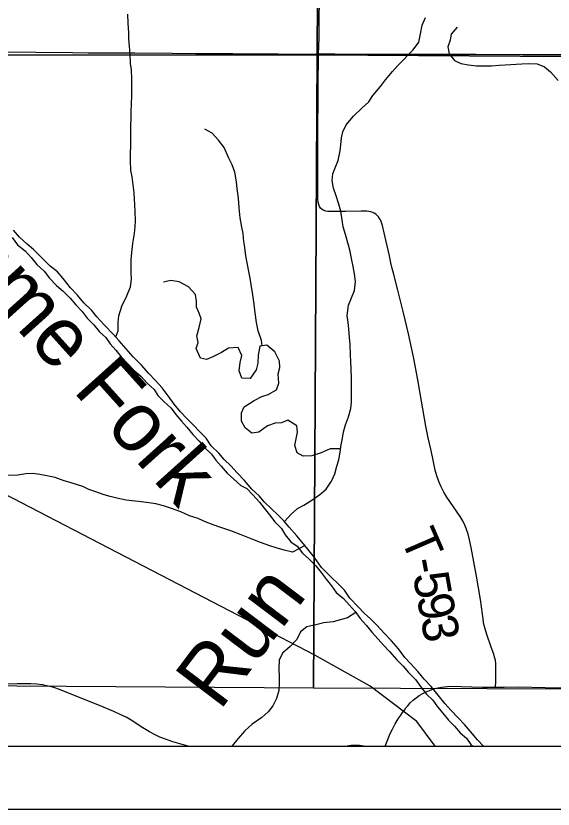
# Model space of a CAD drawing. Extents: x 0 to 34, y 0 to 22.
# Drawn here: x 10.139 to 10.993, y 9.078 to 10.337 of the extents above; entities that cross this region are included whole.
import ezdxf

# ---------------------------------------------------------------- set-up
doc = ezdxf.new("R2010")
doc.units = 0
for name, color, linetype in [('GM_X_County_Road', 7, 'Continuous'), ('GM_X_Interstate_Shield', 7, 'Continuous'), ('GM_X_Major_River', 7, 'Continuous'), ('GM_X_Major_River_Text', 7, 'Continuous'), ('GM_X_Minor_River', 7, 'Continuous'), ('GM_X_Minor_River_Text', 7, 'Continuous'), ('GM_X_Rail_Line', 7, 'Continuous'), ('GM_X_Section', 7, 'Continuous'), ('GM_X_Township_Road', 7, 'Continuous'), ('GM_X_Township_Road_Text', 7, 'Continuous'), ('GM_X_US_Route', 7, 'Continuous'), ('SH_Data', 7, 'Continuous')]:
    doc.layers.add(name, color=color, linetype=linetype)

msp = doc.modelspace()

# ---------------------------------------------------------------- linework, layer by layer
at = {"layer": 'GM_X_County_Road'}
msp.add_lwpolyline([(10.4132, 9.1775), (10.4036, 9.18), (10.3887, 9.1844), (10.3769, 9.1884), (10.3682, 9.1919), (10.3597, 9.1958), (10.3514, 9.2003), (10.3408, 9.2067), (10.3225, 9.2186), (10.3145, 9.2233), (10.3063, 9.2275), (10.295, 9.2326), (10.272, 9.2419), (10.2576, 9.2477), (10.2086, 9.2674), (10.1999, 9.2704), (10.1909, 9.2729), (10.1819, 9.2747), (10.1727, 9.2758), (10.1634, 9.2764), (10.151, 9.2765), (10.1417, 9.2764), (10.1231, 9.2761)], dxfattribs=at)
at = {"layer": 'GM_X_Interstate_Shield'}
msp.add_line((10.6653, 9.1775), (10.6917, 9.1775), dxfattribs=at)
msp.add_arc((10.6785, 9.1043), 0.0744, 79.7646, 100.2354, dxfattribs=at)
at = {"layer": 'GM_X_Major_River'}
for points in [[(10.8821, 9.1775), (10.8727, 9.1878), (10.8616, 9.2007), (10.8517, 9.212), (10.8415, 9.2226), (10.83, 9.2347), (10.8209, 9.2445), (10.8102, 9.2586), (10.7988, 9.2722), (10.7878, 9.2839), (10.7783, 9.2953), (10.7661, 9.3085), (10.7573, 9.3183), (10.7471, 9.332), (10.736, 9.3448), (10.725, 9.3566), (10.7128, 9.3698), (10.7025, 9.3796), (10.6926, 9.3887), (10.6828, 9.3985), (10.6698, 9.4125), (10.6611, 9.425), (10.6519, 9.4349), (10.6394, 9.4466), (10.6249, 9.4614), (10.6135, 9.4769), (10.6032, 9.4905), (10.5937, 9.5019), (10.5857, 9.5117), (10.5735, 9.5253), (10.5648, 9.5352), (10.5552, 9.5446), (10.5454, 9.5541), (10.5343, 9.565), (10.5256, 9.5749), (10.5142, 9.5858), (10.5024, 9.5991), (10.4906, 9.6116), (10.4807, 9.6226), (10.47, 9.6328), (10.4616, 9.6426), (10.4495, 9.6543), (10.4418, 9.6664), (10.4323, 9.6763), (10.4205, 9.6884), (10.411, 9.6978), (10.4008, 9.7084), (10.3909, 9.7205), (10.3813, 9.7338), (10.3718, 9.7463), (10.3608, 9.7584), (10.3505, 9.7694), (10.3387, 9.7826), (10.3258, 9.7955), (10.3147, 9.8083), (10.3037, 9.8208), (10.2942, 9.8318), (10.2797, 9.8462), (10.2679, 9.8594), (10.2599, 9.8693), (10.2474, 9.8814), (10.2371, 9.8935), (10.2264, 9.9052), (10.2143, 9.92), (10.2055, 9.9306), (10.1937, 9.9396), (10.1804, 9.9532), (10.1675, 9.9661), (10.1576, 9.9744), (10.145, 9.9858), (10.1355, 9.997)], [(10.1336, 9.9852), (10.142, 9.9736), (10.1541, 9.9637), (10.1635, 9.9534), (10.1729, 9.942), (10.185, 9.9313), (10.1921, 9.921), (10.2038, 9.9091), (10.2144, 9.9), (10.2257, 9.8889), (10.2348, 9.8782), (10.2449, 9.8675), (10.2529, 9.8573), (10.2634, 9.8466), (10.2721, 9.8355), (10.2823, 9.8263), (10.2894, 9.8161), (10.2981, 9.8061), (10.3067, 9.7958), (10.3173, 9.7848), (10.3267, 9.7745), (10.3384, 9.7645), (10.3475, 9.7542), (10.3592, 9.7439), (10.3648, 9.734), (10.3742, 9.7245), (10.3859, 9.7142), (10.3935, 9.7039), (10.4025, 9.6936), (10.4108, 9.6841), (10.4202, 9.6726), (10.4304, 9.6616), (10.4387, 9.652), (10.45, 9.6413), (10.4568, 9.6318), (10.4655, 9.6219), (10.4749, 9.6112), (10.4858, 9.6013), (10.4964, 9.5913), (10.5062, 9.5867), (10.5157, 9.5768), (10.5262, 9.565), (10.5337, 9.5555), (10.542, 9.5448), (10.5507, 9.5337), (10.5612, 9.523), (10.5673, 9.5131), (10.5763, 9.5021), (10.5861, 9.4952), (10.5948, 9.4838), (10.605, 9.4746), (10.6155, 9.4639), (10.6242, 9.4532), (10.6321, 9.4426), (10.6404, 9.4319), (10.6479, 9.4216), (10.6596, 9.4117), (10.6687, 9.4021), (10.6781, 9.3911), (10.6864, 9.3804), (10.6962, 9.3693), (10.7048, 9.3583), (10.7146, 9.3472), (10.7233, 9.3377), (10.7327, 9.3278), (10.7444, 9.3148), (10.7542, 9.3045), (10.7629, 9.2942), (10.7738, 9.2831), (10.7821, 9.2721), (10.7915, 9.2603), (10.8017, 9.2507), (10.8089, 9.24), (10.8175, 9.2297), (10.8266, 9.2187), (10.836, 9.2091), (10.8447, 9.1985), (10.8549, 9.1904), (10.862, 9.1802), (10.8651, 9.1775)]]:
    msp.add_lwpolyline(points, dxfattribs=at)
at = {"layer": 'GM_X_Minor_River'}
for points in [[(10.298, 9.8274), (10.3021, 9.8368), (10.3021, 9.85), (10.3028, 9.861), (10.3077, 9.8762), (10.3156, 9.8926), (10.3217, 9.9066), (10.3228, 9.9192), (10.3223, 9.9294), (10.3223, 9.9495), (10.3234, 9.9613), (10.3252, 9.9757), (10.3278, 9.9913), (10.329, 10.0023), (10.3293, 10.0118), (10.3289, 10.0266), (10.3285, 10.0368), (10.3277, 10.0467), (10.3273, 10.0561), (10.3257, 10.069), (10.3242, 10.0812), (10.3222, 10.0914), (10.3214, 10.1074), (10.3214, 10.1191), (10.3218, 10.1301), (10.3221, 10.1415), (10.322, 10.1635), (10.3224, 10.1734), (10.3227, 10.1848), (10.3234, 10.2098), (10.3238, 10.2227), (10.3237, 10.2364), (10.3229, 10.2512), (10.3217, 10.2614), (10.3209, 10.2762), (10.3198, 10.2891), (10.319, 10.3005), (10.3186, 10.3103), (10.3178, 10.3255), (10.317, 10.3396)], [(10.5658, 9.534), (10.5765, 9.5458), (10.5867, 9.5546), (10.5969, 9.5603), (10.6094, 9.5679), (10.6223, 9.5771), (10.6321, 9.5858), (10.6404, 9.5984), (10.6461, 9.6098), (10.6491, 9.6219), (10.6521, 9.6322), (10.6543, 9.6443), (10.6558, 9.6561), (10.6581, 9.6664), (10.6599, 9.6766), (10.6629, 9.6876), (10.6675, 9.7005), (10.6712, 9.7134), (10.6723, 9.7237), (10.6722, 9.7624), (10.6718, 9.7753), (10.6714, 9.7886), (10.671, 9.7984), (10.6705, 9.8151), (10.6694, 9.8261), (10.6682, 9.8402), (10.667, 9.8504), (10.6655, 9.8614), (10.6677, 9.8777), (10.6726, 9.8891), (10.6771, 9.9009), (10.679, 9.9153), (10.677, 9.9275), (10.6751, 9.9392), (10.6724, 9.9517), (10.6705, 9.9627), (10.6674, 9.973), (10.6628, 9.99), (10.6594, 10.0022), (10.6574, 10.0124), (10.6555, 10.0268), (10.652, 10.0397), (10.6478, 10.0511), (10.6436, 10.0632), (10.6417, 10.0757), (10.6428, 10.0863), (10.6462, 10.0958), (10.6511, 10.1072), (10.6544, 10.1228), (10.6552, 10.1323), (10.6563, 10.1433), (10.6585, 10.1528), (10.6638, 10.1642), (10.6755, 10.1775), (10.6891, 10.1912), (10.6997, 10.2007), (10.7062, 10.2106), (10.7183, 10.2247), (10.7262, 10.2353), (10.7375, 10.2486), (10.7458, 10.2582), (10.7704, 10.2829), (10.7795, 10.2954), (10.7817, 10.3084), (10.7847, 10.322), (10.79, 10.3346)], [(10.8401, 10.3192), (10.8307, 10.3077), (10.8288, 10.2983), (10.8254, 10.2876), (10.8273, 10.2766), (10.8361, 10.2664), (10.846, 10.2615), (10.8581, 10.2593), (10.871, 10.2578), (10.8949, 10.2579), (10.9071, 10.2587), (10.9165, 10.2594), (10.9431, 10.261), (10.9537, 10.2615), (10.967, 10.2611), (10.9791, 10.2562), (10.9886, 10.2483), (11.0004, 10.2343)], [(10.5306, 9.8132), (10.5294, 9.8215), (10.524, 9.8371), (10.5213, 9.85), (10.5194, 9.8655), (10.5178, 9.8792), (10.5155, 9.894), (10.5132, 9.9106), (10.5117, 9.9205), (10.5093, 9.9311), (10.507, 9.9425), (10.5047, 9.9558), (10.5028, 9.969), (10.5016, 9.9789), (10.5001, 9.9914), (10.4981, 10.0017), (10.4954, 10.0164), (10.4939, 10.032), (10.4927, 10.0476), (10.4911, 10.0623), (10.49, 10.0733), (10.4869, 10.0889), (10.4831, 10.1006), (10.4773, 10.1124), (10.4701, 10.1279), (10.4613, 10.1397), (10.451, 10.151), (10.4393, 10.157)], [(10.655, 9.6498), (10.6384, 9.6496), (10.624, 9.6431), (10.6096, 9.6385), (10.5956, 9.6381), (10.5861, 9.6434), (10.5826, 9.6547), (10.5845, 9.6657), (10.5867, 9.676), (10.5856, 9.6862), (10.5715, 9.6953), (10.5613, 9.6911), (10.5514, 9.6903), (10.5389, 9.6861), (10.5253, 9.6758), (10.5143, 9.6743), (10.5033, 9.6829), (10.4979, 9.6936), (10.4979, 9.7068), (10.502, 9.7163), (10.5179, 9.7262), (10.53, 9.7327), (10.5403, 9.7358), (10.5531, 9.7434), (10.5569, 9.7541), (10.5557, 9.7685), (10.5587, 9.7787), (10.5583, 9.789), (10.5507, 9.8038), (10.5378, 9.814), (10.5268, 9.8128), (10.5242, 9.7984), (10.5234, 9.7855), (10.5212, 9.7748), (10.5114, 9.7611), (10.4985, 9.7619), (10.4939, 9.7736), (10.4957, 9.7869), (10.4984, 9.7979), (10.4926, 9.8104), (10.4771, 9.8092), (10.4661, 9.8024), (10.4521, 9.7955), (10.4419, 9.7913), (10.4324, 9.7935), (10.4255, 9.8091), (10.4289, 9.8186), (10.427, 9.8288), (10.4303, 9.8421), (10.4337, 9.8558), (10.4303, 9.8652), (10.4264, 9.8747), (10.426, 9.8842), (10.4245, 9.8944), (10.4138, 9.9069), (10.3986, 9.9148), (10.3857, 9.9167), (10.374, 9.914)], [(10.5986, 9.496), (10.5786, 9.4855), (10.5657, 9.4889), (10.5527, 9.4926), (10.5429, 9.4956), (10.5281, 9.5009), (10.5129, 9.5069), (10.4973, 9.5129), (10.4806, 9.5193), (10.4635, 9.5254), (10.4529, 9.5291), (10.4388, 9.5344), (10.429, 9.5389), (10.4149, 9.5434), (10.4016, 9.5495), (10.3868, 9.5547), (10.3739, 9.5589), (10.3617, 9.5622), (10.3504, 9.5641), (10.339, 9.5652), (10.3287, 9.5663), (10.3147, 9.5682), (10.2999, 9.5711), (10.2893, 9.5738), (10.2794, 9.5768), (10.265, 9.5817), (10.2555, 9.585), (10.2456, 9.59), (10.2289, 9.5952), (10.2148, 9.5993), (10.2019, 9.6039), (10.1913, 9.6061), (10.1776, 9.6087), (10.1666, 9.6102), (10.1552, 9.6098), (10.1427, 9.6078), (10.1168, 9.6073)], [(10.6793, 9.3895), (10.6661, 9.3814), (10.6566, 9.3784), (10.6434, 9.3749), (10.6282, 9.3733), (10.6157, 9.3703), (10.6017, 9.3668), (10.5915, 9.3592), (10.5858, 9.3466), (10.5752, 9.3356), (10.5627, 9.3253), (10.5574, 9.3143), (10.5571, 9.3006), (10.5575, 9.2877), (10.5576, 9.2775), (10.5568, 9.2657), (10.5531, 9.2532), (10.5474, 9.2414), (10.5402, 9.2319), (10.53, 9.2232), (10.5149, 9.2125), (10.5028, 9.2018), (10.4918, 9.1893), (10.4827, 9.1779), (10.4825, 9.1775)]]:
    msp.add_lwpolyline(points, dxfattribs=at)
at = {"layer": 'GM_X_Rail_Line'}
msp.add_lwpolyline([(10.805, 9.1775), (10.7763, 9.2168), (10.7021, 9.273), (10.6139, 9.322), (10.4117, 9.4273), (10.1211, 9.5782), (10.0825, 9.6016), (10.0422, 9.6272), (10.0025, 9.6582), (9.9676, 9.6941), (9.9058, 9.7623), (9.8351, 9.846), (9.7824, 9.9117), (9.5366, 10.2052), (9.4517, 10.3134), (9.3656, 10.4485), (9.1289, 10.8193), (9.1079, 10.8523)], dxfattribs=at)
at = {"layer": 'GM_X_Section'}
for points in [[(9.6203, 11.2953), (10.6237, 11.2801), (10.6178, 10.275), (9.605, 10.2746)], [(10.6237, 11.2801), (11.5914, 11.2691), (11.591, 11.2544), (11.5843, 10.269), (10.6178, 10.275)], [(10.6178, 10.275), (10.6118, 9.2695), (9.5908, 9.2763), (9.605, 10.2746)], [(10.6178, 10.275), (11.5843, 10.269), (11.5847, 10.2523), (11.5779, 9.2661), (10.6118, 9.2695)]]:
    msp.add_lwpolyline(points, close=True, dxfattribs=at)
at = {"layer": 'GM_X_Township_Road'}
for points in [[(10.6202, 10.2765), (10.621, 10.3016), (10.6212, 10.3108), (10.6218, 10.3818), (10.6221, 10.3958), (10.6222, 10.4141), (10.6223, 10.4328), (10.6223, 10.4483), (10.6223, 10.4701), (10.6225, 10.4918), (10.6227, 10.5104), (10.623, 10.5352), (10.6232, 10.5569), (10.6233, 10.5756), (10.6234, 10.588), (10.6234, 10.6097), (10.6233, 10.6408), (10.624, 10.7185), (10.6242, 10.7496), (10.6242, 10.7744), (10.6242, 10.7868), (10.6238, 10.8039), (10.6234, 10.8246)], [(10.9012, 9.2711), (10.9014, 9.2803), (10.9014, 9.2873), (10.9018, 9.2966), (10.9018, 9.3025), (10.9017, 9.3081), (10.9008, 9.3141), (10.8997, 9.319), (10.8982, 9.3234), (10.8943, 9.3346), (10.8872, 9.3548), (10.8844, 9.3639), (10.883, 9.369), (10.8822, 9.3739), (10.8813, 9.3797), (10.8804, 9.3871), (10.8774, 9.4106), (10.8708, 9.4472), (10.8624, 9.4931), (10.8598, 9.5052), (10.8575, 9.5142), (10.8546, 9.5229), (10.8523, 9.5286), (10.8495, 9.5341), (10.8448, 9.542), (10.8345, 9.5575), (10.8239, 9.5729), (10.819, 9.5809), (10.8146, 9.5892), (10.811, 9.5978), (10.8079, 9.6067), (10.8054, 9.6157), (10.8008, 9.637), (10.7982, 9.6491), (10.7941, 9.6673), (10.7906, 9.6857), (10.7837, 9.7255), (10.7779, 9.7592), (10.7707, 9.7957), (10.7628, 9.8322), (10.7552, 9.8655), (10.746, 9.9016), (10.7389, 9.9287), (10.7369, 9.9361), (10.7348, 9.945), (10.7325, 9.956), (10.7243, 9.9923), (10.7215, 10.0044), (10.7197, 10.0103), (10.7185, 10.0131), (10.717, 10.0154), (10.7151, 10.018), (10.7131, 10.0201), (10.7109, 10.0221), (10.7086, 10.0235), (10.7061, 10.0247), (10.7033, 10.0257), (10.7001, 10.0266), (10.6967, 10.0268), (10.6878, 10.0268), (10.6629, 10.0263), (10.6411, 10.0262), (10.6349, 10.0266), (10.6317, 10.027), (10.6285, 10.0278), (10.6256, 10.0294), (10.6232, 10.0317), (10.6214, 10.0345), (10.6203, 10.0376), (10.6197, 10.0407), (10.6191, 10.047), (10.6188, 10.0719), (10.6188, 10.103), (10.6189, 10.1403), (10.6192, 10.2242), (10.6194, 10.2398), (10.6198, 10.2615), (10.6202, 10.2739), (10.6202, 10.2765)], [(10.7259, 9.1775), (10.7271, 9.1804), (10.734, 9.1974), (10.7374, 9.2043), (10.7415, 9.2127), (10.7447, 9.218), (10.7477, 9.2226), (10.7505, 9.2269), (10.7534, 9.2311), (10.7563, 9.2349), (10.7589, 9.2384), (10.7616, 9.2416), (10.7657, 9.2461), (10.7704, 9.2503), (10.7753, 9.2543), (10.78, 9.2577), (10.7857, 9.2612), (10.7909, 9.2638), (10.7965, 9.2661), (10.8028, 9.2686), (10.8094, 9.2701), (10.8153, 9.2713), (10.8246, 9.2724), (10.8345, 9.2728), (10.8466, 9.2724), (10.8806, 9.2712), (10.9012, 9.2711)], [(10.9012, 9.2711), (10.9148, 9.2714), (10.937, 9.2715), (10.9799, 9.2705), (11.0234, 9.2701), (11.0637, 9.2694), (11.1103, 9.269), (11.1289, 9.2688), (11.1537, 9.2686), (11.1785, 9.269), (11.1925, 9.2688), (11.2006, 9.2684), (11.225, 9.2674), (11.2435, 9.2674), (11.2653, 9.2671), (11.2985, 9.2666), (11.3275, 9.266), (11.3456, 9.2661)]]:
    msp.add_lwpolyline(points, dxfattribs=at)
at = {"layer": 'GM_X_US_Route'}
for points in [[(10.1126, 10.28), (10.2292, 10.2788), (10.254, 10.2784), (10.3286, 10.2781), (10.3877, 10.2777), (10.425, 10.2772), (10.4841, 10.2771), (10.5557, 10.2769), (10.593, 10.2764), (10.6202, 10.2765), (10.6458, 10.2765), (10.6707, 10.2764), (10.7329, 10.2761), (10.7889, 10.2762), (10.8604, 10.2763), (10.8704, 10.2762)], [(10.8704, 10.2762), (10.9443, 10.2758), (11.0065, 10.2756), (11.0438, 10.2755), (11.0605, 10.2753), (11.0687, 10.2753), (11.1215, 10.2751), (11.1525, 10.2751), (11.1898, 10.2748), (11.2365, 10.2749), (11.2519, 10.2749), (11.2892, 10.2744), (11.3326, 10.2746), (11.3476, 10.2746), (11.3606, 10.2742), (11.3855, 10.2738), (11.4072, 10.2736), (11.4663, 10.2724), (11.4974, 10.2718), (11.513, 10.271), (11.5254, 10.2697), (11.5408, 10.2673), (11.5714, 10.2615), (11.5886, 10.2585)]]:
    msp.add_lwpolyline(points, dxfattribs=at)
at = {"layer": 'SH_Data'}
for p, q in [((9.1079, 9.1775), (15.9079, 9.1775)), ((9.0079, 9.0775), (16.0079, 9.0775))]:
    msp.add_line(p, q, dxfattribs=at)

# ---------------------------------------------------------------- texts
at = {"layer": 'GM_X_Major_River_Text'}
msp.add_text('Jerome Fork', height=0.094729, rotation=311.9915, dxfattribs=at).set_placement((9.9224, 10.0819))
at = {"layer": 'GM_X_Minor_River_Text'}
msp.add_text('Run', height=0.09473, rotation=52.8904, dxfattribs=at).set_placement((10.463, 9.2321))
at = {"layer": 'GM_X_Township_Road_Text'}
for s, rotation, p in [('T', 293.3742, (10.7494, 9.5083)), ('-', 280.4312, (10.7653, 9.4726)), ('5', 280.3281, (10.7695, 9.4496)), ('9', 280.276, (10.7758, 9.4152)), ('3', 280.2597, (10.782, 9.3808))]:
    msp.add_text(s, height=0.0568, rotation=rotation, dxfattribs=at).set_placement(p)

doc.saveas('drawing.dxf')
